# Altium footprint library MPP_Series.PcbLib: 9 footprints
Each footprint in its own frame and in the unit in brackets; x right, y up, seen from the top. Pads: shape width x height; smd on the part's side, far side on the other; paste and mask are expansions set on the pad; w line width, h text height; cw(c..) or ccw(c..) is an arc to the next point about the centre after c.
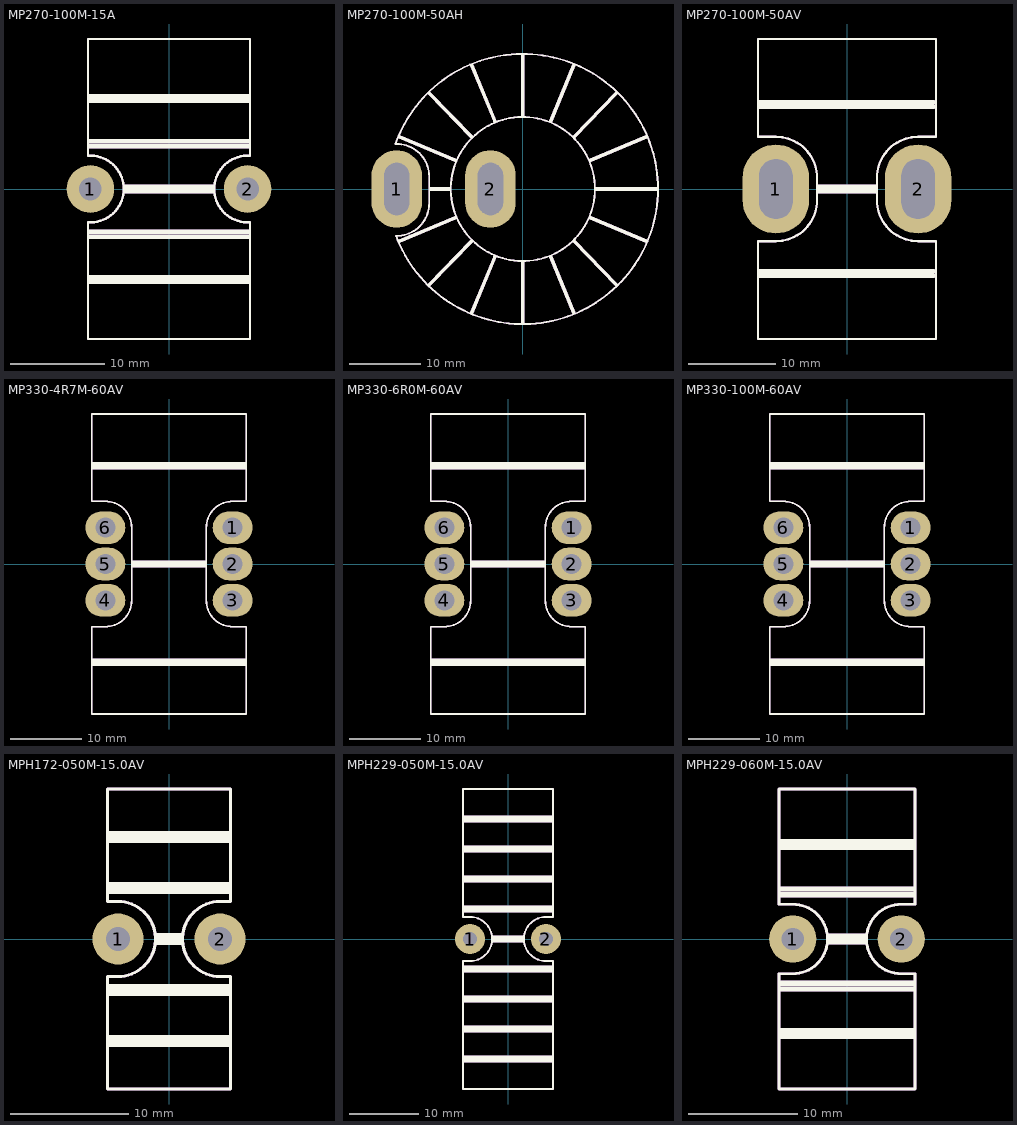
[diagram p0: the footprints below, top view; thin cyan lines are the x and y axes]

## MP270-100M-15A [mil]
pads (2):
  round 200 hole 95: 1(-330,0) 2(330,0)
Top Overlay:
  lines w10: -340,-630 -340,-140 ; -340,140 -340,630 ; -339.97,-139.64 ccw(c-330,0) -339.97,139.64 ; -335,-630 335,-630 ; -335,630 335,630 ; 340,-630 340,-139.64 cw(c330,0) 340,139.64 340,630
  lines w19.68: -334,-390 334,-390 ; -334,-370 334,-370 ; -334,-200 334,-200 ; -334,-180 334,-180 ; -334,180 334,180 ; -334,200 334,200 ; -334,370 334,370 ; -334,390 334,390 ; -185,-10 185,-10 ; -185,10 185,10
Mechanical 29:
  lines w10: -340,-630 -340,-140 ; -340,140 -340,630 ; -339.97,-139.64 ccw(c-330,0) -339.97,139.64 ; -335,-630 335,-630 ; -335,630 335,630 ; 340,-630 340,-139.64 cw(c330,0) 340,139.64 340,630
  lines w19.68: -334,-390 334,-390 ; -334,-370 334,-370 ; -334,-200 334,-200 ; -334,-180 334,-180 ; -334,180 334,180 ; -334,200 334,200 ; -334,370 334,370 ; -334,390 334,390 ; -185,-10 185,-10 ; -185,10 185,10
  text "'.Designator'" at -1750,-64.83 h400

## MP270-100M-50AH [mil]
pads (2):
  oval 280x430 hole 290 slot 140 at 0 deg: 1(-700,0) 2(-180,0)
Top Overlay:
  circle w10: c0,0 r400
  circle w10: c0,0 r400
  lines w10: -700,-260 ccw(c-700,-80) -520,-80 ; -700,-260 ccw(c-700,-80) -520,-80 ; -700,-260 -703.3,-260 -700,-260 ; -700,250 cw(c-700,70) -520,70 ; -700,250 cw(c-700,70) -520,70 ; -700,250 -706.68,250 -700,250 ; -520,-80 -520,70 ; -520,-80 -520,70 ; 735.44,147.09 ccw(c0,0) -707.06,250.13 cw(c0,0) 735.44,147.09 ; 735.44,147.09 cw(c0,0) -703.47,-260.06 ccw(c0,0) 735.44,147.09
  lines w19.68: -686.32,-290.81 -375.4,-159.07 -686.32,-290.81 ; -686.32,290.81 -375.4,159.07 -686.32,290.81 ; -518.81,-530.98 -285.1,-289.9 -518.81,-530.98 ; -518.81,530.98 -285.1,289.9 -518.81,530.98 ; -515,0 -405,0 -515,0 ; -282.93,-687.54 -154.86,-375.06 -282.93,-687.54 ; -282.93,687.54 -154.86,375.06 -282.93,687.54 ; 0,-745 0,-405 0,-745 ; 0,405 0,745 0,405 ; 154.86,-375.06 282.93,-687.54 154.86,-375.06 ; 154.86,375.06 282.93,687.54 154.86,375.06 ; 285.1,-289.9 518.81,-530.98 285.1,-289.9 ; 285.1,289.9 518.81,530.98 285.1,289.9 ; 375.4,-159.07 686.32,-290.81 375.4,-159.07 ; 375.4,159.07 686.32,290.81 375.4,159.07 ; 410,0 745,0 410,0
Mechanical 29:
  circle w10: c0,0 r400
  circle w10: c0,0 r400
  lines w10: -700,-260 ccw(c-700,-80) -520,-80 ; -700,-260 ccw(c-700,-80) -520,-80 ; -700,-260 -703.3,-260 -700,-260 ; -700,250 cw(c-700,70) -520,70 ; -700,250 cw(c-700,70) -520,70 ; -700,250 -706.68,250 -700,250 ; -520,-80 -520,70 ; -520,-80 -520,70 ; 735.44,147.09 ccw(c0,0) -707.06,250.13 cw(c0,0) 735.44,147.09 ; 735.44,147.09 cw(c0,0) -703.47,-260.06 ccw(c0,0) 735.44,147.09
  lines w19.68: -686.32,-290.81 -375.4,-159.07 -686.32,-290.81 ; -686.32,290.81 -375.4,159.07 -686.32,290.81 ; -518.81,-530.98 -285.1,-289.9 -518.81,-530.98 ; -518.81,530.98 -285.1,289.9 -518.81,530.98 ; -515,0 -405,0 -515,0 ; -282.93,-687.54 -154.86,-375.06 -282.93,-687.54 ; -282.93,687.54 -154.86,375.06 -282.93,687.54 ; 0,-745 0,-405 0,-745 ; 0,405 0,745 0,405 ; 154.86,-375.06 282.93,-687.54 154.86,-375.06 ; 154.86,375.06 282.93,687.54 154.86,375.06 ; 285.1,-289.9 518.81,-530.98 285.1,-289.9 ; 285.1,289.9 518.81,530.98 285.1,289.9 ; 375.4,-159.07 686.32,-290.81 375.4,-159.07 ; 375.4,159.07 686.32,290.81 375.4,159.07 ; 410,0 745,0 410,0
  text "'.Designator'" at -292,168.17 h400

## MP270-100M-50AV [mil]
pads (2):
  oval 300x400 hole 270 slot 150 at 0 deg: 1(-320,0) 2(320,0)
Top Overlay:
  lines w10: -400,-675 -400,-235 -320,-235 ccw(c-320,-50) -135,-50 -135,50 ccw(c-320,50) -320,235 -400,235 -400,675 400,675 400,235 320,235 ccw(c320,50) 135,50 135,-50 ccw(c320,-50) 320,-235 400,-235 400,-675 -400,-675
  lines w19.68: -394,-390 391,-390 ; -394,-370 391,-370 ; -394,370 391,370 ; -394,390 391,390 ; -130,-10 130,-10 ; -130,10 130,10
Mechanical 29:
  lines w10: -400,-675 -400,-235 -320,-235 ccw(c-320,-50) -135,-50 -135,50 ccw(c-320,50) -320,235 -400,235 -400,675 400,675 400,235 320,235 ccw(c320,50) 135,50 135,-50 ccw(c320,-50) 320,-235 400,-235 400,-675 -400,-675
  lines w19.68: -394,-390 391,-390 ; -394,-370 391,-370 ; -394,370 391,370 ; -394,390 391,390 ; -130,-10 130,-10 ; -130,10 130,10
  text "'.Designator'" at -1750,-64.83 h400

## MP330-4R7M-60AV [mil]
pads (6):
  oval 220x180 hole 109: 1(350,200) 2(350,0) 3(350,-200) 4(-350,-200) 5(-350,0) 6(-350,200)
Top Overlay:
  lines w10: -425,-825 425,-825 425,-345 350,-345 cw(c350,-200) 205,-200 205,200 cw(c350,200) 350,345 425,345 425,825 -425,825 -425,345 -350,345 cw(c-350,200) -205,200 -205,-200 cw(c-350,-200) -350,-345 -425,-345 -425,-825
  lines w19.68: -420,-550 420,-550 ; -420,-530 420,-530 ; -420,530 420,530 ; -420,550 420,550 ; -200,-10 200,-10 ; -200,10 200,10
Mechanical 29:
  lines w10: -425,-825 425,-825 425,-345 350,-345 cw(c350,-200) 205,-200 205,200 cw(c350,200) 350,345 425,345 425,825 -425,825 -425,345 -350,345 cw(c-350,200) -205,200 -205,-200 cw(c-350,-200) -350,-345 -425,-345 -425,-825
  lines w19.68: -420,-550 420,-550 ; -420,-530 420,-530 ; -420,530 420,530 ; -420,550 420,550 ; -200,-10 200,-10 ; -200,10 200,10
  text "'.Designator'" at -1750,-64.83 h400

## MP330-6R0M-60AV [mil]
pads (6):
  oval 220x180 hole 109: 1(350,200) 2(350,0) 3(350,-200) 4(-350,-200) 5(-350,0) 6(-350,200)
Top Overlay:
  lines w10: -425,-825 425,-825 425,-345 350,-345 cw(c350,-200) 205,-200 205,200 cw(c350,200) 350,345 425,345 425,825 -425,825 -425,345 -350,345 cw(c-350,200) -205,200 -205,-200 cw(c-350,-200) -350,-345 -425,-345 -425,-825
  lines w19.68: -420,-550 420,-550 ; -420,-530 420,-530 ; -420,530 420,530 ; -420,550 420,550 ; -200,-10 200,-10 ; -200,10 200,10
Mechanical 29:
  lines w10: -425,-825 425,-825 425,-345 350,-345 cw(c350,-200) 205,-200 205,200 cw(c350,200) 350,345 425,345 425,825 -425,825 -425,345 -350,345 cw(c-350,200) -205,200 -205,-200 cw(c-350,-200) -350,-345 -425,-345 -425,-825
  lines w19.68: -420,-550 420,-550 ; -420,-530 420,-530 ; -420,530 420,530 ; -420,550 420,550 ; -200,-10 200,-10 ; -200,10 200,10
  text "'.Designator'" at -1750,-64.83 h400

## MP330-100M-60AV [mil]
pads (6):
  oval 220x180 hole 109: 1(350,200) 2(350,0) 3(350,-200) 4(-350,-200) 5(-350,0) 6(-350,200)
Top Overlay:
  lines w10: -425,-825 425,-825 425,-345 350,-345 cw(c350,-200) 205,-200 205,200 cw(c350,200) 350,345 425,345 425,825 -425,825 -425,345 -350,345 cw(c-350,200) -205,200 -205,-200 cw(c-350,-200) -350,-345 -425,-345 -425,-825
  lines w19.68: -420,-550 420,-550 ; -420,-530 420,-530 ; -420,530 420,530 ; -420,550 420,550 ; -200,-10 200,-10 ; -200,10 200,10
Mechanical 29:
  lines w10: -425,-825 425,-825 425,-345 350,-345 cw(c350,-200) 205,-200 205,200 cw(c350,200) 350,345 425,345 425,825 -425,825 -425,345 -350,345 cw(c-350,200) -205,200 -205,-200 cw(c-350,-200) -350,-345 -425,-345 -425,-825
  lines w19.68: -420,-550 420,-550 ; -420,-530 420,-530 ; -420,530 420,530 ; -420,550 420,550 ; -200,-10 200,-10 ; -200,10 200,10
  text "'.Designator'" at -1750,-64.83 h400

## MPH172-050M-15.0AV [mil]
pads (2):
  round 170 hole 80: 1(-170,0) 2(170,0)
Top Overlay:
  lines w10: -205,-500 205,-500 205,-125 170,-125 cw(c170,0) 170,125 205,125 205,500 -205,500 -205,125 -170,125 cw(c-170,0) -170,-125 -205,-125 -205,-500
  lines w19.68: -200,-350 200,-350 ; -200,-330 200,-330 ; -200,-180 200,-180 ; -200,-160 200,-160 ; -200,160 200,160 ; -200,180 200,180 ; -200,330 200,330 ; -200,350 200,350 ; -40,-10 40,-10 ; -40,10 40,10
Mechanical 29:
  lines w10: -205,-500 205,-500 205,-125 170,-125 cw(c170,0) 170,125 205,125 205,500 -205,500 -205,125 -170,125 cw(c-170,0) -170,-125 -205,-125 -205,-500
  lines w19.68: -200,-350 200,-350 ; -200,-330 200,-330 ; -200,-180 200,-180 ; -200,-160 200,-160 ; -200,160 200,160 ; -200,180 200,180 ; -200,330 200,330 ; -200,350 200,350 ; -40,-10 40,-10 ; -40,10 40,10
  text "'.Designator'" at -1750,-64.83 h400

## MPH229-050M-15.0AV [mil]
pads (2):
  round 170 hole 80: 1(-215,0) 2(215,0)
Top Overlay:
  lines w10: -255,-850 -255,-125 -215,-125 ccw(c-215,0) -215,125 -255,125 -255,850 255,850 255,125 215,125 ccw(c215,0) 215,-125 255,-125 255,-850 -255,-850
  lines w19.68: -250,-690 250,-690 ; -250,-670 250,-670 ; -250,-520 250,-520 ; -250,-500 250,-500 ; -250,-350 250,-350 ; -250,-330 250,-330 ; -250,-180 250,-180 ; -250,-160 250,-160 ; -250,160 250,160 ; -250,180 250,180 ; -250,330 250,330 ; -250,350 250,350 ; -250,500 250,500 ; -250,520 250,520 ; -250,670 250,670 ; -250,690 250,690 ; -85,-10 85,-10 ; -85,10 85,10
Mechanical 29:
  lines w10: -255,-850 -255,-125 -215,-125 ccw(c-215,0) -215,125 -255,125 -255,850 255,850 255,125 215,125 ccw(c215,0) 215,-125 255,-125 255,-850 -255,-850
  lines w19.68: -250,-690 250,-690 ; -250,-670 250,-670 ; -250,-520 250,-520 ; -250,-500 250,-500 ; -250,-350 250,-350 ; -250,-330 250,-330 ; -250,-180 250,-180 ; -250,-160 250,-160 ; -250,160 250,160 ; -250,180 250,180 ; -250,330 250,330 ; -250,350 250,350 ; -250,500 250,500 ; -250,520 250,520 ; -250,670 250,670 ; -250,690 250,690 ; -85,-10 85,-10 ; -85,10 85,10
  text "'.Designator'" at -1200,175.17 h400

## MPH229-060M-15.0AV [mil]
pads (2):
  round 170 hole 80: 1(-195,0) 2(195,0)
Top Overlay:
  lines w10: -245,-540 245,-540 245,-125 195,-125 cw(c195,0) 195,125 245,125 245,540 -245,540 -245,125 -195,125 cw(c-195,0) -195,-125 -245,-125 -245,-540
  lines w19.68: -240,-350 240,-350 ; -240,-330 240,-330 ; -240,-180 240,-180 ; -240,-160 240,-160 ; -240,160 240,160 ; -240,180 240,180 ; -240,330 240,330 ; -240,350 240,350 ; -65,-10 65,-10 ; -65,10 65,10
Mechanical 29:
  lines w10: -245,-540 245,-540 245,-125 195,-125 cw(c195,0) 195,125 245,125 245,540 -245,540 -245,125 -195,125 cw(c-195,0) -195,-125 -245,-125 -245,-540
  lines w19.68: -240,-350 240,-350 ; -240,-330 240,-330 ; -240,-180 240,-180 ; -240,-160 240,-160 ; -240,160 240,160 ; -240,180 240,180 ; -240,330 240,330 ; -240,350 240,350 ; -65,-10 65,-10 ; -65,10 65,10
  text "'.Designator'" at -1200,175.17 h400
